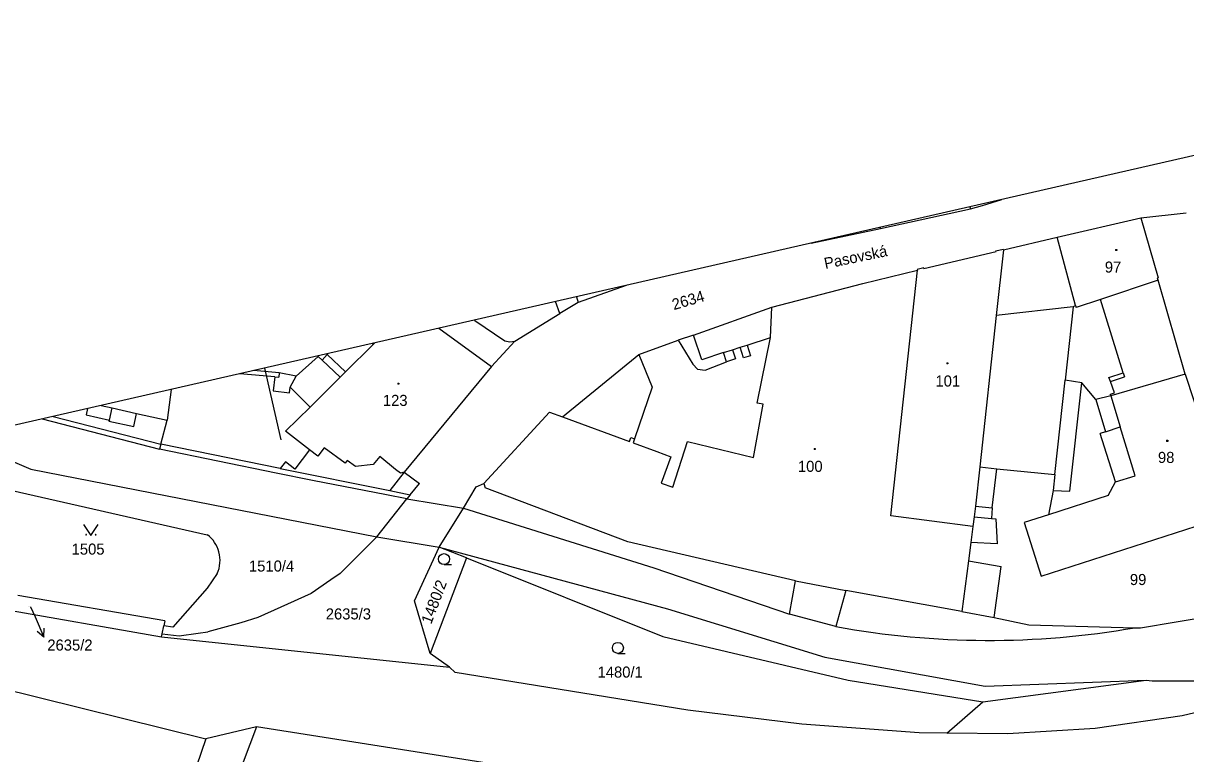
# Model space of a CAD drawing. Extents: x -805730 to -804640, y -1150889 to -1150366.
# Drawn here: x -805353.5 to -805195.8, y -1150558.7 to -1150459.5 of the extents above; entities that cross this region are included whole.
import ezdxf

# ---------------------------------------------------------------- set-up
doc = ezdxf.new("R2010")
doc.units = 0
for name, color, linetype in [('Default', 7, 'Continuous'), ('formát', 7, 'Continuous'), ('kn_celek - Cisla parcel pomocna', 7, 'Continuous'), ('kn_celek - Cisla pozemkovych parcel', 7, 'Continuous'), ('kn_celek - Cisla stavebnich parcel', 7, 'Continuous'), ('kn_celek - Dalsi prvky mapy popis', 7, 'Continuous'), ('kn_celek - Hranice parcel', 7, 'Continuous'), ('kn_celek - Vnitrni kresby', 7, 'Continuous'), ('kn_celek - Znacky budov', 7, 'Continuous'), ('kn_celek - Znacky kultur', 7, 'Continuous')]:
    doc.layers.add(name, color=color, linetype=linetype)

# ---------------------------------------------------------------- blocks, each defined once
blk = doc.blocks.new('304')
at = {"layer": 'Default'}
blk.add_line((-0.1, 0), (9.9, 0), dxfattribs=at)
blk.add_circle((-0.1, 7.5), 7.5, dxfattribs=at)
blk = doc.blocks.new('314')
at = {"layer": 'Default'}
for p, q in [((-10, 15), (0, 0)), ((0, 0), (10, 15))]:
    blk.add_line(p, q, dxfattribs=at)
for centre, start, end in [((-6.2, 1), 360, 180), ((-6.2, 1), 180, 360), ((6.6, 1), 0, 180), ((6.6, 1), 180, 0)]:
    blk.add_arc(centre, 0.5, start, end, dxfattribs=at)
blk = doc.blocks.new('402')
at = {"layer": 'Default'}
for p, q in [((-0.8, 0.8), (0.7, 0.8)), ((-0.8, 0.8), (-0.8, -0.7)), ((0.7, 0.8), (0.7, -0.7)), ((0.7, -0.7), (-0.8, -0.7))]:
    blk.add_line(p, q, dxfattribs=at)
blk = doc.blocks.new('Z61')
at = {"layer": 'Default'}
for p, q in [((0, 0), (30, 0)), ((30, 0), (19.2, 5.3)), ((30, 0), (19.2, -5.3))]:
    blk.add_line(p, q, dxfattribs=at)

msp = doc.modelspace()

# ---------------------------------------------------------------- linework, layer by layer
at = {"layer": 'formát'}
for p, q in [((-805116.05, -1150459.54), (-805730.21, -1150599.91)), ((-805320.77, -1150506.33), (-805318.54, -1150516.08)), ((-805320.77, -1150506.33), (-805318.54, -1150516.08))]:
    msp.add_line(p, q, dxfattribs=at)
at = {"layer": 'kn_celek - Cisla parcel pomocna'}
msp.add_line((-805352.51, -1150538.73), (-805351.91, -1150540.1), dxfattribs=at)
at = {"layer": 'kn_celek - Hranice parcel'}
for p, q in [((-805225.05, -1150484.46), (-805224.96, -1150484.73)), ((-805224.96, -1150484.73), (-805223.35, -1150484.27)), ((-805223.35, -1150484.27), (-805220.73, -1150483.47)), ((-805237.19, -1150487.38), (-805224.96, -1150484.73)), ((-805213.2, -1150488.59), (-805201.85, -1150485.93)), ((-805201.85, -1150485.93), (-805195.7, -1150485.27)), ((-805201.85, -1150485.93), (-805199.52, -1150494.08)), ((-805246.6, -1150489.38), (-805237.19, -1150487.38)), ((-805237.25, -1150487.25), (-805237.19, -1150487.38)), ((-805220.52, -1150490.31), (-805213.2, -1150488.59)), ((-805231.3, -1150492.83), (-805221.49, -1150490.54)), ((-805221.52, -1150490.44), (-805220.54, -1150490.21)), ((-805221.49, -1150490.54), (-805221.52, -1150490.44)), ((-805220.52, -1150490.31), (-805221.48, -1150499.22)), ((-805220.54, -1150490.21), (-805220.52, -1150490.31)), ((-805239.58, -1150494.88), (-805232.18, -1150493.04)), ((-805235.79, -1150526.38), (-805232.18, -1150493.04)), ((-805231.33, -1150492.74), (-805232.2, -1150492.94)), ((-805232.2, -1150492.94), (-805232.18, -1150493.04)), ((-805231.3, -1150492.83), (-805231.33, -1150492.74)), ((-805199.6, -1150494.15), (-805199.52, -1150494.08)), ((-805271.72, -1150495.13), (-805278.19, -1150497.42)), ((-805251.94, -1150498.05), (-805239.58, -1150494.88)), ((-805199.53, -1150494.43), (-805199.6, -1150494.15)), ((-805195.84, -1150507.17), (-805199.53, -1150494.43)), ((-805278.45, -1150496.66), (-805278.19, -1150497.42)), ((-805280.72, -1150498.95), (-805281.27, -1150497.31)), ((-805278.19, -1150497.42), (-805280.72, -1150498.95)), ((-805262.58, -1150501.86), (-805251.94, -1150498.05)), ((-805292.3, -1150499.83), (-805292.24, -1150499.87)), ((-805292.24, -1150499.87), (-805288.15, -1150502.64)), ((-805286.8, -1150502.69), (-805280.72, -1150498.95)), ((-805221.48, -1150499.22), (-805223.7, -1150519.75)), ((-805297.14, -1150500.93), (-805289.97, -1150506.14)), ((-805262.58, -1150501.86), (-805264.65, -1150502.54)), ((-805306.02, -1150503.15), (-805306.18, -1150503)), ((-805305.79, -1150502.91), (-805306.02, -1150503.15)), ((-805289.97, -1150506.14), (-805286.8, -1150502.69)), ((-805288.15, -1150502.64), (-805287.47, -1150502.78)), ((-805287.47, -1150502.78), (-805286.8, -1150502.69)), ((-805269.96, -1150504.51), (-805264.65, -1150502.54)), ((-805313.48, -1150504.77), (-805316.48, -1150507.44)), ((-805312.93, -1150505.26), (-805313.48, -1150504.77)), ((-805312.26, -1150504.49), (-805312.93, -1150505.26)), ((-805312.14, -1150504.36), (-805312.26, -1150504.49)), ((-805280.34, -1150512.95), (-805269.96, -1150504.51)), ((-805318.79, -1150507), (-805322.28, -1150506.68)), ((-805289.97, -1150506.14), (-805301.82, -1150520.48)), ((-805316.48, -1150507.44), (-805318.79, -1150507)), ((-805213.53, -1150520.77), (-805212.14, -1150507.96)), ((-805209.85, -1150508.36), (-805212.14, -1150507.96)), ((-805195.84, -1150507.17), (-805205.93, -1150510.1)), ((-805195.84, -1150507.17), (-805189.61, -1150526.23)), ((-805333.45, -1150509.23), (-805334, -1150513.4)), ((-805207.99, -1150510.6), (-805209.85, -1150508.36)), ((-805205.93, -1150510.1), (-805207.99, -1150510.6)), ((-805291.01, -1150522), (-805282.1, -1150512.3)), ((-805282.1, -1150512.3), (-805280.34, -1150512.95)), ((-805350.96, -1150513.23), (-805335.03, -1150517.32)), ((-805334.86, -1150516.66), (-805334, -1150513.4)), ((-805360.88, -1150516.47), (-805352.47, -1150520.04)), ((-805334.86, -1150516.66), (-805335.03, -1150517.32)), ((-805319.2, -1150520.58), (-805335.03, -1150517.32)), ((-805352.47, -1150520.04), (-805305.51, -1150529.23)), ((-805314.25, -1150521.59), (-805319.2, -1150520.58)), ((-805301.82, -1150520.48), (-805299.73, -1150522)), ((-805223.7, -1150519.75), (-805224.31, -1150525.07)), ((-805223.7, -1150519.75), (-805221.4, -1150519.99)), ((-805221.4, -1150519.99), (-805213.53, -1150520.77)), ((-805213.53, -1150520.77), (-805213.77, -1150522.96)), ((-805357.89, -1150522.31), (-805328.53, -1150528.95)), ((-805304.2, -1150523.53), (-805314.25, -1150521.59)), ((-805301.01, -1150523.52), (-805299.73, -1150522)), ((-805293.79, -1150525.37), (-805292.03, -1150522.45)), ((-805292.03, -1150522.45), (-805291.01, -1150522)), ((-805291.01, -1150522), (-805290.81, -1150522.61)), ((-805301.46, -1150524.06), (-805304.2, -1150523.53)), ((-805301.01, -1150523.52), (-805301.46, -1150524.06)), ((-805301.46, -1150524.06), (-805293.79, -1150525.37)), ((-805271.47, -1150529.92), (-805290.81, -1150522.61)), ((-805213.77, -1150522.96), (-805214.4, -1150526.23)), ((-805224.31, -1150525.07), (-805224.5, -1150526.53)), ((-805224.31, -1150525.07), (-805222.03, -1150525.31)), ((-805222.03, -1150525.31), (-805222.11, -1150526.77)), ((-805224.66, -1150527.82), (-805235.79, -1150526.38)), ((-805224.5, -1150526.53), (-805224.66, -1150527.82)), ((-805222.11, -1150526.77), (-805221.55, -1150526.81)), ((-805221.55, -1150526.81), (-805221.38, -1150530.19)), ((-805214.4, -1150526.23), (-805217.69, -1150527.29)), ((-805217.69, -1150527.29), (-805215.37, -1150534.59)), ((-805215.37, -1150534.59), (-805194.37, -1150527.77)), ((-805305.51, -1150529.23), (-805310.49, -1150534.21)), ((-805305.51, -1150529.23), (-805297.06, -1150530.62)), ((-805248.73, -1150535.19), (-805271.47, -1150529.92)), ((-805224.95, -1150530), (-805225.26, -1150532.48)), ((-805221.38, -1150530.19), (-805224.95, -1150530)), ((-805300.4, -1150537.94), (-805297.06, -1150530.62)), ((-805293.36, -1150532.1), (-805297.06, -1150530.62)), ((-805293.36, -1150532.1), (-805298.31, -1150545.07)), ((-805293.36, -1150532.1), (-805266.73, -1150542.74)), ((-805225.26, -1150532.48), (-805220.83, -1150533.25)), ((-805221.78, -1150540.18), (-805220.83, -1150533.25)), ((-805327.18, -1150534.23), (-805328.55, -1150536.22)), ((-805311.75, -1150535.07), (-805314.43, -1150536.92)), ((-805310.49, -1150534.21), (-805311.75, -1150535.07)), ((-805328.55, -1150536.22), (-805333.2, -1150541.48)), ((-805249.53, -1150539.72), (-805248.73, -1150535.19)), ((-805241.9, -1150536.5), (-805243.25, -1150541.41)), ((-805226.15, -1150539.38), (-805241.9, -1150536.5)), ((-805361.9, -1150538.09), (-805334.75, -1150542.8)), ((-805334.31, -1150540.65), (-805354.23, -1150537.22)), ((-805314.43, -1150536.92), (-805318.56, -1150538.77)), ((-805298.31, -1150545.07), (-805300.4, -1150537.94)), ((-805318.56, -1150538.77), (-805321.68, -1150540.17)), ((-805243.25, -1150541.41), (-805249.53, -1150539.72)), ((-805226.15, -1150539.38), (-805221.78, -1150540.18)), ((-805201.89, -1150541.59), (-805191.45, -1150539.81)), ((-805334.67, -1150542.4), (-805334.45, -1150541.31)), ((-805334.31, -1150540.65), (-805334.45, -1150541.31)), ((-805333.2, -1150541.48), (-805334.45, -1150541.31)), ((-805323.98, -1150540.92), (-805328.46, -1150542.15)), ((-805321.68, -1150540.17), (-805323.98, -1150540.92)), ((-805221.78, -1150540.18), (-805217.08, -1150541.2)), ((-805217.08, -1150541.2), (-805202.69, -1150541.57)), ((-805334.75, -1150542.8), (-805334.67, -1150542.4)), ((-805334.75, -1150542.8), (-805295.66, -1150546.92)), ((-805334.67, -1150542.4), (-805332.36, -1150542.69)), ((-805332.36, -1150542.69), (-805329.77, -1150542.33)), ((-805329.77, -1150542.33), (-805328.46, -1150542.15)), ((-805266.73, -1150542.74), (-805241.56, -1150548.67)), ((-805202.69, -1150541.57), (-805201.89, -1150541.59)), ((-805295.66, -1150546.92), (-805298.31, -1150545.07)), ((-805368.66, -1150546.75), (-805328.74, -1150556.64)), ((-805294.92, -1150547.64), (-805295.66, -1150546.92)), ((-805263.35, -1150552.74), (-805294.92, -1150547.64)), ((-805241.56, -1150548.67), (-805223.29, -1150551.65)), ((-805223.29, -1150551.65), (-805201.13, -1150548.68)), ((-805201.13, -1150548.68), (-805200.33, -1150548.77)), ((-805200.33, -1150548.77), (-805189.88, -1150548.76)), ((-805184.73, -1150550.79), (-805196.27, -1150553.55)), ((-805228.17, -1150555.87), (-805223.29, -1150551.65)), ((-805247.85, -1150554.66), (-805263.35, -1150552.74)), ((-805196.27, -1150553.55), (-805208.08, -1150555.25)), ((-805321.88, -1150555.04), (-805328.74, -1150556.64)), ((-805321.88, -1150555.04), (-805324.61, -1150562.25)), ((-805239.54, -1150567.94), (-805321.88, -1150555.04)), ((-805231.93, -1150555.83), (-805247.85, -1150554.66)), ((-805208.08, -1150555.25), (-805219.93, -1150555.97)), ((-805328.74, -1150556.64), (-805331.2, -1150563.91)), ((-805228.17, -1150555.87), (-805231.93, -1150555.83)), ((-805219.93, -1150555.97), (-805228.17, -1150555.87))]:
    msp.add_line(p, q, dxfattribs=at)
for centre, radius, start, end in [((-805331.16, -1150532.41), 4.35, 14.9638, 52.7547), ((-805331.12, -1150532.46), 4.32, 335.768, 15.6731)]:
    msp.add_arc(centre, radius, start, end, dxfattribs=at)
at = {"layer": 'kn_celek - Vnitrni kresby'}
for p, q in [((-805210.72, -1150497.84), (-805213.2, -1150488.59)), ((-805199.53, -1150494.43), (-805207.34, -1150497.02)), ((-805207.34, -1150497.02), (-805210.65, -1150498.12)), ((-805204.24, -1150507), (-805207.34, -1150497.02)), ((-805252.13, -1150502.2), (-805251.94, -1150498.05)), ((-805211.06, -1150498.01), (-805221.48, -1150499.22)), ((-805211.06, -1150498.01), (-805212.14, -1150507.96)), ((-805210.72, -1150497.84), (-805211.06, -1150498.01)), ((-805210.72, -1150497.84), (-805210.65, -1150498.12)), ((-805292.24, -1150499.87), (-805292.24, -1150499.81)), ((-805261.45, -1150505.2), (-805262.58, -1150501.86)), ((-805309.76, -1150506.84), (-805306.02, -1150503.15)), ((-805264.65, -1150502.54), (-805262.66, -1150505.79)), ((-805257.25, -1150503.85), (-805256.23, -1150503.52)), ((-805256.23, -1150503.52), (-805255.28, -1150503.21)), ((-805255.77, -1150504.97), (-805256.23, -1150503.52)), ((-805255.28, -1150503.21), (-805252.13, -1150502.2)), ((-805255.28, -1150503.21), (-805254.82, -1150504.66)), ((-805253.94, -1150511.08), (-805252.13, -1150502.2)), ((-805309.76, -1150506.84), (-805312.26, -1150504.49)), ((-805269.96, -1150504.51), (-805268.17, -1150508.91)), ((-805258.48, -1150504.24), (-805261.45, -1150505.2)), ((-805258.48, -1150504.24), (-805257.25, -1150503.85)), ((-805258.08, -1150505.48), (-805258.48, -1150504.24)), ((-805256.85, -1150505.09), (-805258.08, -1150505.48)), ((-805257.25, -1150503.85), (-805256.85, -1150505.09)), ((-805254.82, -1150504.66), (-805255.77, -1150504.97)), ((-805310.5, -1150507.58), (-805312.93, -1150505.26)), ((-805262.66, -1150505.79), (-805262.03, -1150506.48)), ((-805262.03, -1150506.48), (-805260.99, -1150506.6)), ((-805260.99, -1150506.6), (-805258.08, -1150505.48)), ((-805319.39, -1150507.54), (-805324.14, -1150507.11)), ((-805319.39, -1150507.54), (-805319.59, -1150509.43)), ((-805319.39, -1150507.54), (-805318.84, -1150507.59)), ((-805318.79, -1150507), (-805318.84, -1150507.59)), ((-805317.29, -1150508.95), (-805316.48, -1150507.44)), ((-805310.5, -1150507.58), (-805314.59, -1150511.62)), ((-805309.76, -1150506.84), (-805310.5, -1150507.58)), ((-805206.19, -1150507.6), (-805204.24, -1150507)), ((-805205.98, -1150508.17), (-805206.19, -1150507.6)), ((-805205.98, -1150508.17), (-805204.07, -1150507.53)), ((-805205.43, -1150509.7), (-805205.98, -1150508.17)), ((-805204.24, -1150507), (-805204.07, -1150507.53)), ((-805319.59, -1150509.43), (-805317.38, -1150509.71)), ((-805317.38, -1150509.71), (-805317.29, -1150508.95)), ((-805317.29, -1150508.95), (-805314.59, -1150511.62)), ((-805268.17, -1150508.91), (-805270.55, -1150515.93)), ((-805211.49, -1150523.03), (-805209.85, -1150508.36)), ((-805205.98, -1150509.9), (-805205.43, -1150509.7)), ((-805205.93, -1150510.1), (-805205.98, -1150509.9)), ((-805342.94, -1150511.4), (-805341.45, -1150511.73)), ((-805254.43, -1150518.46), (-805253.09, -1150511.23)), ((-805253.09, -1150511.23), (-805253.94, -1150511.08)), ((-805207.99, -1150510.6), (-805206.66, -1150514.99)), ((-805205.93, -1150510.1), (-805204.66, -1150514.32)), ((-805349.47, -1150512.9), (-805334.86, -1150516.66)), ((-805344.79, -1150511.82), (-805344.98, -1150512.68)), ((-805344.98, -1150512.68), (-805341.82, -1150513.39)), ((-805341.82, -1150513.39), (-805341.45, -1150511.73)), ((-805341.45, -1150511.73), (-805338.12, -1150512.48)), ((-805338.52, -1150514.27), (-805338.12, -1150512.48)), ((-805338.12, -1150512.48), (-805334, -1150513.4)), ((-805314.59, -1150511.62), (-805317.94, -1150514.92)), ((-805280.34, -1150512.95), (-805271.26, -1150516.29)), ((-805341.82, -1150513.39), (-805341.88, -1150513.52)), ((-805341.88, -1150513.52), (-805338.52, -1150514.27)), ((-805206.66, -1150514.99), (-805204.66, -1150514.32)), ((-805202.62, -1150520.97), (-805204.66, -1150514.32)), ((-805314.66, -1150517.45), (-805317.94, -1150514.92)), ((-805271.26, -1150516.29), (-805271.06, -1150515.74)), ((-805271.06, -1150515.74), (-805270.55, -1150515.93)), ((-805270.55, -1150515.93), (-805270.75, -1150516.48)), ((-805206.66, -1150514.99), (-805207.36, -1150515.23)), ((-805205.32, -1150521.79), (-805207.36, -1150515.23)), ((-805318.66, -1150519.95), (-805334.86, -1150516.66)), ((-805314.66, -1150517.45), (-805316.66, -1150520.06)), ((-805313.54, -1150518.31), (-805314.66, -1150517.45)), ((-805312.68, -1150517.18), (-805313.54, -1150518.31)), ((-805309.82, -1150519.26), (-805312.68, -1150517.18)), ((-805270.75, -1150516.48), (-805267.56, -1150517.66)), ((-805267.56, -1150517.66), (-805265.65, -1150518.36)), ((-805265.35, -1150522.5), (-805263.39, -1150516.29)), ((-805263.39, -1150516.29), (-805254.43, -1150518.46)), ((-805317.92, -1150519.07), (-805318.66, -1150519.95)), ((-805316.66, -1150520.06), (-805317.92, -1150519.07)), ((-805309.57, -1150518.86), (-805309.82, -1150519.26)), ((-805308.42, -1150519.7), (-805309.57, -1150518.86)), ((-805305.14, -1150518.34), (-805306.02, -1150519.43)), ((-805303.01, -1150520.08), (-805305.14, -1150518.34)), ((-805265.65, -1150518.36), (-805266.97, -1150521.94)), ((-805318.66, -1150519.95), (-805303.76, -1150522.97)), ((-805306.02, -1150519.43), (-805308.42, -1150519.7)), ((-805301.82, -1150520.48), (-805303.76, -1150522.97)), ((-805302.34, -1150520.59), (-805303.01, -1150520.08)), ((-805301.82, -1150520.48), (-805302.34, -1150520.59)), ((-805222.03, -1150525.31), (-805221.4, -1150519.99)), ((-805266.97, -1150521.94), (-805265.35, -1150522.5)), ((-805206.3, -1150523.63), (-805205.32, -1150521.79)), ((-805205.32, -1150521.79), (-805202.62, -1150520.97)), ((-805305.51, -1150529.23), (-805301.46, -1150524.06)), ((-805303.76, -1150522.97), (-805301.01, -1150523.52)), ((-805206.3, -1150523.63), (-805214.4, -1150526.23)), ((-805213.77, -1150522.96), (-805211.49, -1150523.03)), ((-805297.06, -1150530.62), (-805293.79, -1150525.37)), ((-805293.79, -1150525.37), (-805267.96, -1150533.46)), ((-805224.5, -1150526.53), (-805222.11, -1150526.77)), ((-805224.66, -1150527.82), (-805224.95, -1150530)), ((-805297.06, -1150530.62), (-805266.09, -1150539.03)), ((-805267.96, -1150533.46), (-805249.53, -1150539.72)), ((-805225.26, -1150532.48), (-805226.15, -1150539.38)), ((-805248.73, -1150535.19), (-805241.9, -1150536.5)), ((-805266.09, -1150539.03), (-805244.74, -1150545.56)), ((-805244.74, -1150545.56), (-805223, -1150549.49)), ((-805223, -1150549.49), (-805201.13, -1150548.68))]:
    msp.add_line(p, q, dxfattribs=at)
msp.add_arc((-805222.52, -1150428.12), 115.17, 259.6324, 279.9156, dxfattribs=at)
msp.add_arc((-805222.52, -1150428.12), 115.17, 259.6324, 279.9156, dxfattribs=at)

# ---------------------------------------------------------------- block references
at = {"layer": 'kn_celek - Cisla parcel pomocna', "xscale": 0.10000000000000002, "yscale": 0.10000000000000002, "rotation": -66.39975000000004}
msp.add_blockref('Z61', (-805351.91, -1150540.1), dxfattribs=at)
at = {"layer": 'kn_celek - Znacky budov', "xscale": 0.1, "yscale": 0.10000000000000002}
for p in [(-805205.21, -1150490.32), (-805228.11, -1150505.7), (-805302.62, -1150508.46), (-805198.28, -1150516.21), (-805246.11, -1150517.32)]:
    msp.add_blockref('402', p, dxfattribs=at)
at = {"layer": 'kn_celek - Znacky kultur', "xscale": 0.1, "yscale": 0.10000000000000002}
for name, p in [('314', (-805344.34, -1150529.05)), ('304', (-805296.4, -1150533.01)), ('304', (-805272.81, -1150545.06))]:
    msp.add_blockref(name, p, dxfattribs=at)

# ---------------------------------------------------------------- texts
at = {"layer": 'kn_celek - Cisla parcel pomocna'}
msp.add_text('2635/2', height=1.5, dxfattribs=at).set_placement((-805350.24, -1150544.67))
at = {"layer": 'kn_celek - Cisla pozemkovych parcel'}
for s, height, rotation, p in [('2634', 1.5, 16.46, (-805265.22, -1150498.48)), ('1480/2', 1.5, 69.3, (-805298.16, -1150541.19)), ('2635/2', 0.1, 351, (-805352.79, -1150538.74))]:
    msp.add_text(s, height=height, rotation=rotation, dxfattribs=at).set_placement(p)
for s, p in [('1505', (-805346.94, -1150531.65)), ('1510/4', (-805322.88, -1150533.95)), ('99', (-805203.35, -1150535.78)), ('2635/3', (-805312.46, -1150540.45)), ('1480/1', (-805275.58, -1150548.34))]:
    msp.add_text(s, height=1.5, dxfattribs=at).set_placement(p)
at = {"layer": 'kn_celek - Cisla stavebnich parcel'}
for s, p in [('97', (-805206.75, -1150493.38)), ('101', (-805229.73, -1150508.84)), ('123', (-805304.71, -1150511.47)), ('98', (-805199.54, -1150519.21)), ('100', (-805248.39, -1150520.42))]:
    msp.add_text(s, height=1.5, dxfattribs=at).set_placement(p)
at = {"layer": 'kn_celek - Dalsi prvky mapy popis'}
msp.add_text('Pasovská', height=1.5, rotation=11.7188, dxfattribs=at).set_placement((-805244.67, -1150492.89))

doc.saveas('drawing.dxf')
